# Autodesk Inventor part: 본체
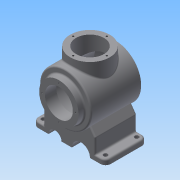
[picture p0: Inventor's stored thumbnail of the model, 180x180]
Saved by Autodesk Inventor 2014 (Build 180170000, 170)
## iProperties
Created: 2018-08
Part Number: 본체
Material: 일반
Document SubType Name: Modeling
Designer: 601-06
Density: 1 g/cm^3
Appearance: 기본값
Author: 601-06
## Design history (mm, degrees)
sketch "스케치1"
  geometry: L1 (0, 0)-(80, 0); L2 (80, 0)-(80, 140); L3 (80, 140)-(0, 140); L4 (0, 140)-(0, 0)
  constraints: 8 end point, 1 horizontal, 1 parallel, 1 perpendicular
  dimensions: "d0" = 80 distance of L1.start L1.end; "d1" = 140 distance of L1.end L2.end; "d2" = 80 distance of L2.end L3.end
extrude "돌출1" new body sketch "스케치1" distance "d3" = 10; taper "d4" = 0 deg
node "작업 평면2"
sketch "스케치2"
  geometry: L1 (-8, 44)-(-8, 32); L2 (-20, 44)-(-20, 82); L3 (-20, 82)-(100, 82); L4 (-20, 44)-(-8, 44); L5 (-8, 32)-(88.671, 32); A1 r 116 centre (-16, 82) between (88.671, 32) and (100, 82); 1 further point
  constraints: 10 end point, 2 parallel, 2 point on circle, 1 centre point, 1 perpendicular
  dimensions: "d16" = 32 vertical distance of point (80, 0) L1.end; "d18" = 88 horizontal distance of L1.end point (80, 0); "d29" = 12 distance of L1.start L2.start; "d31" = 44 vertical distance of point (80, 0) L2.start; "d32" = 100 horizontal distance of point (80, 0) L2.end; "d36" = 82 vertical distance of point (80, 0) L3.end; "d38" = 32 vertical distance of point (80, 0) L5.end; "d39" = 116 radius of A1; "d40" = 8.67091 horizontal distance of point (80, 0) L5.end; "d41" = 20 horizontal distance of point (80, 0) L3.end
revolve "회전1" sketch "스케치2" stored, may be unused: angle "d42" = 90 deg
sketch "스케치3"
  geometry: L1 (-20, 82)-(-20, 55); L2 (-20, 82)-(-16, 82); L3 (-20, 55)-(2, 55); L4 (2, 55)-(2, 42); L5 (2, 42)-(87.542, 42); L6 (-20, 82)-(95, 82); L7 (88.671, 132)-(-8, 132) reference; A1 r 111 centre (-16, 82) between (87.542, 42) and (95, 82); A2 r 116 centre (-16, 82) between (88.671, 32) and (88.671, 132) reference; 1 further point
  constraints: 12 end point, 3 parallel, 2 perpendicular, 2 point on circle, 1 centre point, 1 coincident
  dimensions: "d45" = 27 distance of L1.start L1.end; "d46" = 4 distance of L1.start L2.end; "d48" = 222 diameter of A1; "d49" = 22 distance of L1.end L3.end; "d50" = 13 distance of L3.end L4.end; "d51" = 15 horizontal distance of point (80, 0) L6.end; "d52" = 7.54226 horizontal distance of point (80, 0) L5.end; "d53" = 82 vertical distance of point (80, 0) L6.end
revolve "회전2" sketch "스케치3" stored, may be unused: angle "d54" = 90 deg
node "작업 평면3"
sketch "스케치6"
  geometry: L1 (0, 0)-(0, 10); L2 (0, 10)-(70, 10); L3 (20, 0)-(20, 38.563); L4 (20, 0)-(70, 0); L5 (70, 0)-(70, 32); L6 (20, 38.563)-(29.696, 52.41); C1 r 40 at (70, 82) reference; A1 r 50 centre (70, 82) between (29.696, 52.41) and (70, 32)
  constraints: 12 end point, 2 perpendicular, 2 point on circle, 1 centre point, 1 coincident, 1 horizontal, 1 vertical
  dimensions: "d78" = 10 distance of L1.start L1.end; "d81" = 20 distance of L1.start L3.start; "d82" = 50 distance of L3.start L4.end; "d84" = 70 distance of L1.start L4.end; "d85" = 145 deg angle of L3 L6; "d86" = 38.56296 vertical distance of L1.start L3.end; "d87" = 52.40997 vertical distance of L1.start L6.end; "d88" = 50 radius of A1
extrude "돌출2" join sketch "스케치6" stored distance "d89" = 80; taper "d90" = 0 deg
sketch "스케치7"
  geometry: L1 (0, 0)-(140, 0) reference; L2 (70, 0)-(42.5, 0); C1 r 12.5 at (42.5, 0)
  constraints: 2 end point, 1 centre point, 1 coincident, 1 midpoint, 1 point on line
  dimensions: "d92" = 27.5 distance of L2.start L2.end; "d94" = 25 diameter of C1
extrude "돌출3" cut sketch "스케치7" distance "d95" = 80; taper "d96" = 0 deg
sketch "스케치8"
  geometry: L1 (-85, 0)-(0, 0) reference; L2 (-70, 0)-(-47.5, 0); C1 r 17.5 at (-47.5, 0); 1 further point
  constraints: 2 end point, 2 point on line, 1 centre point, 1 coincident
  dimensions: "d97" = 22.5 distance of L2.start L2.end; "d98" = 35 diameter of C1; "d99" = 92.5 distance of point (-140, 0) C1.centre
extrude "돌출4" cut sketch "스케치8" distance "d100" = 80; taper "d101" = 0 deg
node "작업 평면4"
sketch "스케치9"
  geometry: C1 r 38 at (40, 70); 1 further point
  constraints: 1 centre point
  dimensions: "d103" = 76 diameter of C1; "d104" = 40 horizontal distance of point (0, 0) C1.centre; "d105" = 70 vertical distance of point (0, 0) C1.centre
extrude "돌출5" join sketch "스케치9" stored distance "d106" = 80; taper "d107" = 0 deg
sketch "스케치10"
  geometry: C1 r 38 at (0, 0) reference; C2 r 27 at (0, 0); 1 further point
  constraints: 1 centre point, 1 coincident
  dimensions: "d108" = 54 diameter of C2
extrude "돌출6" cut sketch "스케치10" distance "d109" = 80; taper "d110" = 0 deg
fillet "모깎기1" dims "d111" = 10
sketch "스케치12"
  geometry: C1 r 4 at (-70, -10); A1 r 10 centre (-70, -10) between (-70, 0) and (-80, -10) reference; 1 further point
  constraints: 1 centre point, 1 coincident
  dimensions: "d112" = 8 diameter of C1
extrude "돌출7" cut sketch "스케치12" distance "d113" = 80; taper "d114" = 0 deg
node "작업 평면5"
node "작업 평면6"
fillet "모깎기2" dims "d115" = 3
fillet "모깎기3" dims "d116" = 3
fillet "모깎기4" dims "d117" = 3
fillet "모깎기5" dims "d118" = 3
fillet "모깎기6" dims "d119" = 3
fillet "모깎기7" dims "d120" = 3
fillet "모깎기8" dims "d121" = 3
sketch "스케치13"
  geometry: C1 r 27 at (0, 0) reference; 2 further points
  dimensions: "d123" = 32.5 distance of C1.centre point (0, 32.5); "d124" = 40 horizontal distance of point (40, 70) point (0, 32.5)
hole "구멍1" sketch "스케치13" at (0, 32.5) diameter "d125" = 3.242; stored, may be unused: countersink angle "d129" = 90 deg, drill point angle "d131" = 118 deg; dims "d126" = 8, "d127" = 4, "d128" = 2, "d130" = 10
node "작업축1"
sketch "스케치14"
  geometry: L1 (70, -82)-(60, -82) reference; C1 r 27 at (0, 0) reference; 2 further points
  dimensions: "d136" = 82 distance from line of L1 point (32.5, 0); "d137" = 32.5 distance of C1.centre point (32.5, 0)
node "작업축2"
hole "구멍2" sketch "스케치14" diameter "d138" = 3.242; stored, may be unused: countersink angle "d142" = 90 deg, drill point angle "d144" = 118 deg; dims "d139" = 8, "d140" = 4, "d141" = 2, "d143" = 10
node "솔리드1"
mirror "대칭1"
mirror "대칭2"
mirror "대칭3"
pattern_circular "원형 패턴1" dims angle "d133" = 360 deg
pattern_circular "원형 패턴2" dims angle "d146" = 360 deg
node "투영된 루프2"
other parameters: "d57" = 55 deg, "d80" = 55 deg, "d102" = 147
